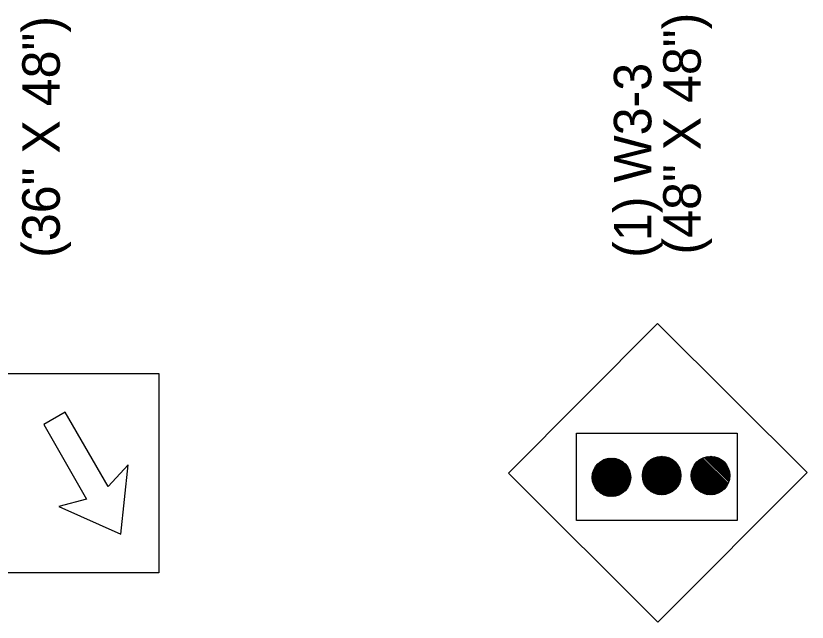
# Model space of a CAD drawing. Extents: x 1678017 to 1687792, y 404433 to 413488.
# Drawn here: x 1680445.4 to 1680572, y 404833.7 to 404930.8 of the extents above; entities that cross this region are included whole.
import ezdxf

# ---------------------------------------------------------------- set-up
doc = ezdxf.new("R2010")
doc.units = 0
doc.layers.add('Default', color=7, linetype='Continuous')

msp = doc.modelspace()

# ---------------------------------------------------------------- linework, layer by layer
at = {"layer": 'Default'}
for p, q in [((1680548.02, 404881.52), (1680524.18, 404857.58)), ((1680548.02, 404881.52), (1680571.97, 404857.66)), ((1680542.9, 404854.77), (1680538.54, 404859.13)), ((1680542.99, 404854.87), (1680538.64, 404859.22)), ((1680543.08, 404854.97), (1680538.74, 404859.31)), ((1680543.16, 404855.08), (1680538.85, 404859.39)), ((1680543.24, 404855.19), (1680538.96, 404859.47)), ((1680543.31, 404855.31), (1680539.08, 404859.54)), ((1680543.38, 404855.43), (1680539.2, 404859.61)), ((1680543.45, 404855.55), (1680539.32, 404859.68)), ((1680543.51, 404855.68), (1680539.45, 404859.74)), ((1680543.56, 404855.82), (1680539.59, 404859.79)), ((1680543.61, 404855.96), (1680539.73, 404859.84)), ((1680543.65, 404856.1), (1680539.87, 404859.88)), ((1680543.69, 404856.26), (1680540.03, 404859.92)), ((1680543.72, 404856.42), (1680540.19, 404859.95)), ((1680543.74, 404856.58), (1680540.35, 404859.97)), ((1680543.75, 404856.76), (1680540.53, 404859.98)), ((1680543.76, 404856.95), (1680540.72, 404859.99)), ((1680543.75, 404857.15), (1680540.92, 404859.98)), ((1680543.72, 404857.36), (1680541.13, 404859.95)), ((1680543.68, 404857.6), (1680541.37, 404859.91)), ((1680543.6, 404857.86), (1680541.63, 404859.83)), ((1680543.49, 404858.17), (1680541.94, 404859.71)), ((1680543.26, 404858.59), (1680542.36, 404859.49)), ((1680550.74, 404854.87), (1680546.39, 404859.22)), ((1680550.84, 404854.96), (1680546.48, 404859.32)), ((1680550.93, 404855.05), (1680546.57, 404859.41)), ((1680551.02, 404855.15), (1680546.67, 404859.5)), ((1680551.11, 404855.25), (1680546.77, 404859.59)), ((1680551.19, 404855.36), (1680546.88, 404859.67)), ((1680551.27, 404855.47), (1680546.99, 404859.75)), ((1680551.34, 404855.59), (1680547.11, 404859.82)), ((1680551.41, 404855.71), (1680547.23, 404859.89)), ((1680551.48, 404855.83), (1680547.35, 404859.96)), ((1680551.54, 404855.96), (1680547.48, 404860.02)), ((1680551.59, 404856.1), (1680547.62, 404860.07)), ((1680551.64, 404856.24), (1680547.76, 404860.12)), ((1680551.68, 404856.39), (1680547.91, 404860.16)), ((1680551.72, 404856.54), (1680548.06, 404860.2)), ((1680551.75, 404856.7), (1680548.22, 404860.23)), ((1680551.77, 404856.87), (1680548.39, 404860.25)), ((1680551.79, 404857.04), (1680548.56, 404860.27)), ((1680551.79, 404857.23), (1680548.75, 404860.27)), ((1680551.78, 404857.43), (1680548.95, 404860.26)), ((1680551.75, 404857.64), (1680549.16, 404860.23)), ((1680551.71, 404857.88), (1680549.4, 404860.19)), ((1680551.64, 404858.14), (1680549.66, 404860.12)), ((1680551.52, 404858.45), (1680549.97, 404860)), ((1680551.29, 404858.87), (1680550.39, 404859.77)), ((1680558.48, 404854.82), (1680554.14, 404859.16)), ((1680558.58, 404854.91), (1680554.23, 404859.26)), ((1680558.68, 404855), (1680554.32, 404859.36)), ((1680558.77, 404855.09), (1680554.42, 404859.45)), ((1680558.86, 404855.2), (1680554.52, 404859.54)), ((1680558.95, 404855.3), (1680554.62, 404859.63)), ((1680559.03, 404855.41), (1680554.73, 404859.71)), ((1680559.1, 404855.52), (1680554.84, 404859.78)), ((1680559.18, 404855.64), (1680554.96, 404859.86)), ((1680559.24, 404855.76), (1680555.08, 404859.92)), ((1680559.31, 404855.89), (1680555.21, 404859.98)), ((1680559.42, 404856.16), (1680555.48, 404860.09)), ((1680559.46, 404856.3), (1680555.63, 404860.14)), ((1680559.5, 404856.45), (1680555.77, 404860.18)), ((1680559.54, 404856.61), (1680555.93, 404860.22)), ((1680559.56, 404856.77), (1680556.09, 404860.24)), ((1680559.58, 404856.94), (1680556.26, 404860.26)), ((1680559.59, 404857.12), (1680556.45, 404860.27)), ((1680559.59, 404857.32), (1680556.64, 404860.27)), ((1680559.57, 404857.52), (1680556.84, 404860.25)), ((1680559.54, 404857.74), (1680557.07, 404860.22)), ((1680559.48, 404857.99), (1680557.31, 404860.16)), ((1680559.39, 404858.27), (1680557.59, 404860.07)), ((1680559.24, 404858.61), (1680557.93, 404859.92)), ((1680558.83, 404859.21), (1680558.54, 404859.51)), ((1680541.76, 404854.01), (1680537.78, 404857.99)), ((1680541.89, 404854.07), (1680537.84, 404858.12)), ((1680542.02, 404854.13), (1680537.9, 404858.25)), ((1680542.15, 404854.19), (1680537.96, 404858.38)), ((1680542.27, 404854.26), (1680538.03, 404858.5)), ((1680542.38, 404854.34), (1680538.11, 404858.61)), ((1680542.5, 404854.41), (1680538.18, 404858.73)), ((1680542.6, 404854.5), (1680538.27, 404858.83)), ((1680542.71, 404854.58), (1680538.35, 404858.94)), ((1680542.81, 404854.67), (1680538.44, 404859.04)), ((1680549.5, 404854.2), (1680545.72, 404857.98)), ((1680549.65, 404854.25), (1680545.77, 404858.13)), ((1680549.79, 404854.3), (1680545.82, 404858.27)), ((1680549.93, 404854.35), (1680545.87, 404858.41)), ((1680550.06, 404854.41), (1680545.93, 404858.54)), ((1680550.18, 404854.48), (1680546, 404858.66)), ((1680550.3, 404854.54), (1680546.06, 404858.78)), ((1680550.42, 404854.62), (1680546.14, 404858.9)), ((1680550.53, 404854.7), (1680546.22, 404859.01)), ((1680550.64, 404854.78), (1680546.3, 404859.12)), ((1680557.22, 404854.18), (1680553.5, 404857.9)), ((1680557.37, 404854.22), (1680553.54, 404858.05)), ((1680557.51, 404854.27), (1680553.59, 404858.19)), ((1680557.65, 404854.32), (1680553.64, 404858.33)), ((1680557.78, 404854.38), (1680553.7, 404858.46)), ((1680557.91, 404854.44), (1680553.76, 404858.59)), ((1680558.04, 404854.51), (1680553.83, 404858.71)), ((1680558.15, 404854.58), (1680553.9, 404858.83)), ((1680558.27, 404854.65), (1680553.97, 404858.95)), ((1680558.38, 404854.73), (1680554.05, 404859.06)), ((1680524.18, 404857.58), (1680548.11, 404833.72)), ((1680540.81, 404853.82), (1680537.59, 404857.04)), ((1680540.63, 404853.82), (1680537.59, 404856.86)), ((1680540.99, 404853.83), (1680537.6, 404857.22)), ((1680540.43, 404853.83), (1680537.6, 404856.66)), ((1680541.16, 404853.86), (1680537.63, 404857.39)), ((1680541.32, 404853.89), (1680537.66, 404857.55)), ((1680541.47, 404853.92), (1680537.69, 404857.7)), ((1680541.62, 404853.97), (1680537.74, 404857.85)), ((1680548.85, 404854.1), (1680545.62, 404857.33)), ((1680548.66, 404854.1), (1680545.62, 404857.14)), ((1680548.46, 404854.11), (1680545.63, 404856.94)), ((1680549.02, 404854.12), (1680545.64, 404857.5)), ((1680548.25, 404854.13), (1680545.65, 404856.73)), ((1680549.19, 404854.14), (1680545.66, 404857.67)), ((1680549.35, 404854.17), (1680545.69, 404857.83)), ((1680571.97, 404857.66), (1680548.11, 404833.72)), ((1680556.54, 404854.1), (1680553.42, 404857.22)), ((1680556.35, 404854.1), (1680553.42, 404857.03)), ((1680556.73, 404854.11), (1680553.43, 404857.41)), ((1680556.14, 404854.12), (1680553.44, 404856.82)), ((1680556.9, 404854.12), (1680553.45, 404857.58)), ((1680557.06, 404854.15), (1680553.47, 404857.74)), ((1680555.92, 404854.16), (1680553.48, 404856.6)), ((1680540.21, 404853.85), (1680537.62, 404856.44)), ((1680539.98, 404853.9), (1680537.67, 404856.21)), ((1680539.72, 404853.97), (1680537.74, 404855.95)), ((1680539.41, 404854.09), (1680537.86, 404855.64)), ((1680548.01, 404854.18), (1680545.7, 404856.49)), ((1680547.75, 404854.25), (1680545.77, 404856.23)), ((1680547.44, 404854.37), (1680545.89, 404855.92)), ((1680547.02, 404854.6), (1680546.12, 404855.5)), ((1680555.67, 404854.21), (1680553.54, 404856.35)), ((1680555.39, 404854.31), (1680553.63, 404856.07)), ((1680555.03, 404854.47), (1680553.79, 404855.71)), ((1680538.99, 404854.31), (1680538.08, 404855.22))]:
    msp.add_line(p, q, dxfattribs=at)
for points in [[(1680420.47, 404873.51), (1680468.28, 404873.51), (1680468.28, 404841.64), (1680420.47, 404841.64)], [(1680449.91, 404865.37), (1680456.73, 404853.43), (1680452.27, 404852.23), (1680462.19, 404847.81), (1680463.39, 404858.9), (1680460.16, 404855.45), (1680453.3, 404867.35)], [(1680535.06, 404850.01), (1680535.06, 404863.95), (1680560.79, 404863.95), (1680560.79, 404850.01)]]:
    msp.add_lwpolyline(points, close=True, dxfattribs=at)
for centre in [(1680540.67, 404856.9), (1680548.7, 404857.18), (1680556.51, 404857.18)]:
    msp.add_circle(centre, 3.08, dxfattribs=at)

# ---------------------------------------------------------------- texts
for s, p in [('(36" X 48")', (1680452.45, 404892.04)), ('(48" X 48")', (1680554.95, 404892.57)), ('(1) W3-3', (1680547.05, 404892.04))]:
    msp.add_text(s, height=6, rotation=90, dxfattribs=at).set_placement(p)

doc.saveas('drawing.dxf')
